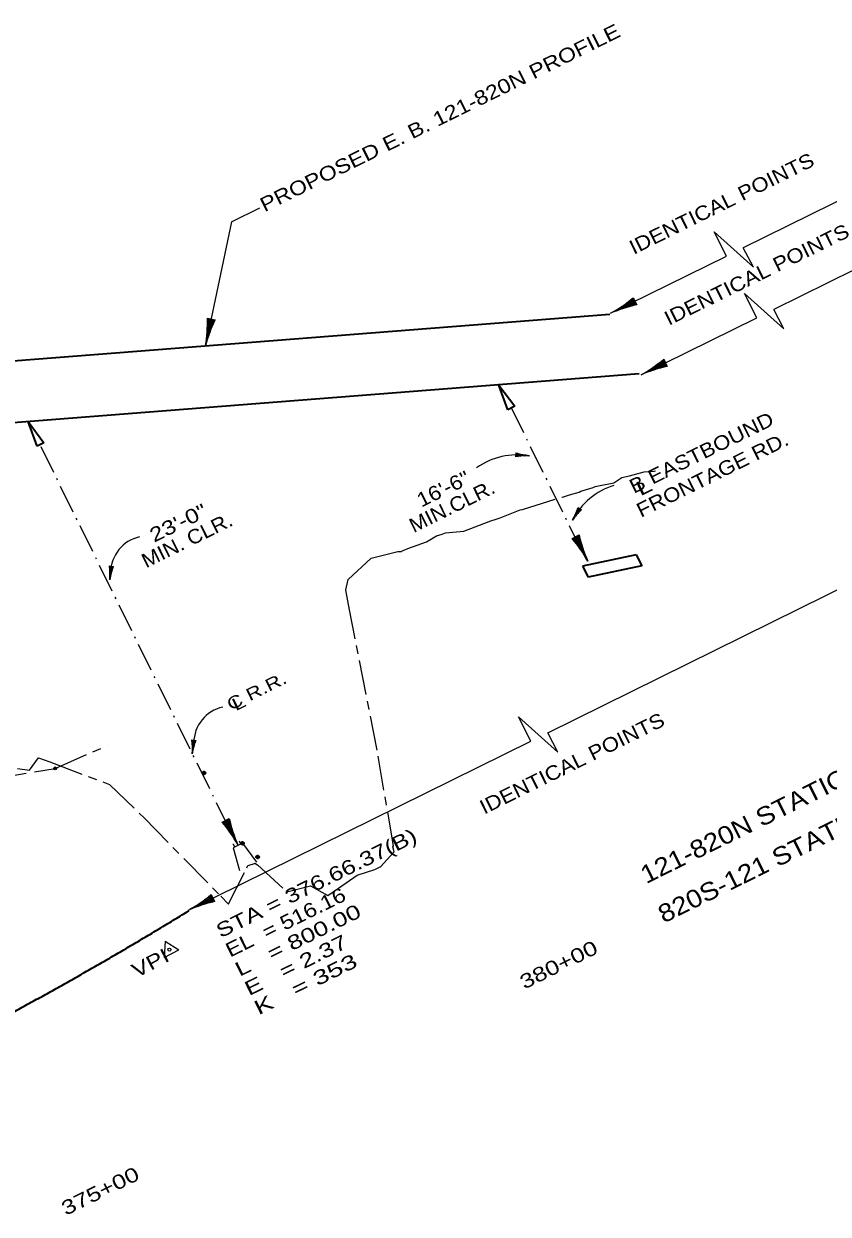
# Model space of a CAD drawing. Extents: x 2356431 to 2371438, y 6972864 to 6982525.
# Drawn here: x 2365783 to 2366570, y 6976942 to 6978106 of the extents above; entities that cross this region are included whole.
import ezdxf
from ezdxf.enums import TextEntityAlignment as Align

# ---------------------------------------------------------------- set-up
doc = ezdxf.new("R2010")
doc.units = 0
doc.header["$LTSCALE"] = 5.6
doc.header["$PDMODE"] = 32
doc.header["$PDSIZE"] = 2.8
for name, pattern in [('DASH_DOUBLE_DOT', [9.2, 5, -1.2, 0.3, -1.2, 0.3, -1.2]), ('DOT_DASHED', [7.7, 5, -1.2, 0.3, -1.2]), ('LONG_DASH_SHORT_DASH', [9.9, 6, -1.2, 1.5, -1.2]), ('LONG_DASHED', [7.5, 6, -1.5])]:
    doc.linetypes.add(name, pattern=pattern)
for name, color, linetype, lineweight in [('1', 7, 'Continuous', 25), ('2', 7, 'Continuous', 35), ('4', 7, 'LONG_DASHED', 35), ('44', 7, 'Continuous', 13), ('52', 7, 'Continuous', 25), ('53', 7, 'Continuous', 13), ('55', 7, 'Continuous', 13), ('61', 7, 'Continuous', 13)]:
    doc.layers.add(name, color=color, linetype=linetype, lineweight=lineweight)

msp = doc.modelspace()

# ---------------------------------------------------------------- linework, layer by layer
at = {"layer": '1'}
for p, q in [((2366380.572, 6977835.032), (2366358.046, 6977823.896)), ((2366381.015, 6977834.137), (2366365.579, 6977826.505)), ((2366380.129, 6977835.929), (2366366.95, 6977829.413)), ((2366379.687, 6977836.825), (2366372.019, 6977833.034)), ((2366381.459, 6977833.24), (2366372.741, 6977828.929)), ((2366379.243, 6977837.721), (2366376.4, 6977836.317)), ((2366381.902, 6977832.342), (2366377.632, 6977830.232)), ((2366378.933, 6977838.35), (2366382.327, 6977831.483)), ((2366410.296, 6977774.805), (2366387.77, 6977763.669)), ((2366410.739, 6977773.91), (2366395.303, 6977766.278)), ((2366409.853, 6977775.702), (2366396.674, 6977769.186)), ((2366409.411, 6977776.598), (2366401.743, 6977772.807)), ((2366411.183, 6977773.013), (2366402.465, 6977768.702)), ((2366408.967, 6977777.494), (2366406.124, 6977776.09)), ((2366411.626, 6977772.115), (2366407.356, 6977770.005)), ((2366408.657, 6977778.123), (2366412.051, 6977771.256)), ((2366319.08, 6977602.965), (2366325.95, 6977606.356)), ((2366319.708, 6977603.274), (2366321.11, 6977600.432)), ((2366320.604, 6977603.717), (2366324.39, 6977596.047)), ((2366321.501, 6977604.16), (2366328.006, 6977590.978)), ((2366322.399, 6977604.603), (2366333.52, 6977582.069)), ((2366323.296, 6977605.046), (2366330.916, 6977589.604)), ((2366324.191, 6977605.488), (2366328.495, 6977596.768)), ((2366325.088, 6977605.93), (2366327.196, 6977601.66)), ((2365967.732, 6977251.48), (2365945.206, 6977240.344)), ((2365968.175, 6977250.585), (2365952.739, 6977242.953)), ((2365967.289, 6977252.377), (2365954.11, 6977245.861)), ((2365966.847, 6977253.273), (2365959.179, 6977249.482)), ((2365968.619, 6977249.688), (2365959.901, 6977245.377)), ((2365966.403, 6977254.169), (2365963.56, 6977252.765)), ((2365969.062, 6977248.79), (2365964.792, 6977246.68)), ((2365966.094, 6977254.799), (2365969.488, 6977247.932))]:
    msp.add_line(p, q, dxfattribs=at)
at = {"layer": '1', "linetype": 'DOT_DASHED', "lineweight": 13}
msp.add_line((2365983.806, 6977319.446), (2365798.207, 6977695.508), dxfattribs=at)
at = {"layer": '1', "lineweight": 35}
for p, q in [((2366381.786, 6977587.003), (2366329.311, 6977575.832)), ((2366381.786, 6977587.003), (2366387.11, 6977576.215)), ((2366329.311, 6977575.832), (2366334.635, 6977565.044)), ((2366387.11, 6977576.215), (2366334.635, 6977565.044))]:
    msp.add_line(p, q, dxfattribs=at)
at = {"layer": '1', "linetype": 'LONG_DASH_SHORT_DASH'}
msp.add_line((2365813.438, 6977378.181), (2365864.499, 6977400.494), dxfattribs=at)
at = {"layer": '1', "linetype": 'LONG_DASHED'}
msp.add_line((2365710.484, 6977360.825), (2365813.438, 6977378.181), dxfattribs=at)
at = {"layer": '1', "lineweight": 13}
for p, q in [((2365976.874, 6977325.669), (2365983.744, 6977329.06)), ((2365977.501, 6977325.979), (2365978.904, 6977323.136)), ((2365978.398, 6977326.421), (2365982.183, 6977318.751)), ((2365979.296, 6977326.864), (2365985.801, 6977313.682)), ((2365980.193, 6977327.307), (2365991.313, 6977304.773)), ((2365981.089, 6977327.75), (2365988.71, 6977312.308)), ((2365981.985, 6977328.191), (2365986.289, 6977319.472)), ((2365982.882, 6977328.634), (2365984.99, 6977324.363)), ((2365993.659, 6977306.712), (2365992.964, 6977306.369)), ((2365993.659, 6977306.712), (2365994.156, 6977306.958)), ((2365994.942, 6977304.113), (2365993.724, 6977306.581)), ((2365987.919, 6977303.88), (2365987.271, 6977303.56)), ((2365987.587, 6977300.483), (2365993.832, 6977278.257)), ((2365989.202, 6977301.28), (2365987.917, 6977303.883)), ((2365987.919, 6977303.88), (2365988.329, 6977304.082)), ((2365996.668, 6977304.965), (2366010.512, 6977286.489))]:
    msp.add_line(p, q, dxfattribs=at)
at = {"layer": '1', "linetype": 'LONG_DASH_SHORT_DASH'}
msp.add_lwpolyline([(2365776.602, 6977378.009), (2365788.527, 6977376.384), (2365797.098, 6977388.517), (2365797.262, 6977388.568), (2365808.166, 6977384.427), (2365866.729, 6977362.512), (2365900.468, 6977329.749), (2365975.432, 6977253.209), (2365982.865, 6977245.28), (2365982.974, 6977245.284), (2365983.329, 6977246.258), (2366000.892, 6977280.846), (2366001.988, 6977283.075), (2366002.119, 6977283.126), (2366003.234, 6977283.51), (2366008.318, 6977285.254), (2366008.72, 6977285.478), (2366011.481, 6977283.796), (2366040.032, 6977257.402), (2366063.277, 6977263.159), (2366080.054, 6977253.838), (2366090.534, 6977261.093), (2366108.85, 6977273.754), (2366126.118, 6977279.373), (2366131.309, 6977281.735), (2366131.533, 6977281.892), (2366144.75, 6977296.338), (2366145.157, 6977296.574), (2366143.591, 6977301.548), (2366144.328, 6977302.314), (2366128.386, 6977396.093), (2366101.51, 6977533.231), (2366098.726, 6977547.148), (2366097.801, 6977552.856), (2366100.109, 6977562.969), (2366122.635, 6977583.654), (2366127.922, 6977585.01), (2366148.734, 6977590.07), (2366151.866, 6977590.166), (2366152.085, 6977590.286), (2366152.493, 6977590.5), (2366152.935, 6977590.711), (2366155.594, 6977591.787), (2366158.36, 6977593.095), (2366176.56, 6977599.786), (2366186.396, 6977605.545), (2366191.97, 6977607.314), (2366195.282, 6977608.512), (2366213.202, 6977610.011), (2366239.638, 6977620.057), (2366244.672, 6977621.945), (2366248.72, 6977623.235), (2366268.169, 6977630.874), (2366270.468, 6977631.435), (2366309.663, 6977643.381), (2366316.578, 6977645.503), (2366325.961, 6977648.365), (2366327.702, 6977649.289), (2366339.831, 6977652.825), (2366341.723, 6977653.668), (2366359.811, 6977657.449), (2366367.679, 6977662.608), (2366375.096, 6977664.326), (2366389.651, 6977668.144), (2366399.335, 6977668.772), (2366400.712, 6977669.122)], dxfattribs=at)
at = {"layer": '1'}
for centre, start, end in [((2366286.411, 6977949.256), 299.14996, 309.83601), ((2366414.27, 6977690.628), 102.77679, 113.46284), ((2366316.135, 6977889.03), 299.14996, 309.83601), ((2366443.993, 6977630.401), 102.77679, 113.46284), ((2366208.112, 6977510.518), 29.11143, 39.79748), ((2366466.826, 6977638.202), 192.73827, 203.42432), ((2365873.572, 6977365.705), 299.14996, 309.83601), ((2366001.43, 6977107.076), 102.77679, 113.46284)]:
    msp.add_arc(centre, 144.431, start, end, dxfattribs=at)
at = {"layer": '1', "lineweight": 13}
for centre, radius, start, end in [((2366265.859, 6977614.665), 70.06, 80.64351, 125.05271), ((2366381.09, 6977587.98), 70.06, 107.48304, 151.89224), ((2365903.913, 6977569.144), 36.259, 102.58429, 179.17976), ((2365985.245, 6977402.662), 36.259, 102.58429, 179.17976), ((2365865.905, 6977233.222), 144.431, 29.11143, 39.79748), ((2366124.619, 6977360.906), 144.431, 192.73827, 203.42432)]:
    msp.add_arc(centre, radius, start, end, dxfattribs=at)
at = {"layer": '2', "lineweight": 13}
for p, q in [((2365986.056, 6977912.411), (2366013.825, 6977926.116)), ((2365986.056, 6977912.411), (2365960.543, 6977791.527)), ((2365962.341, 6977818.364), (2365969.834, 6977816.769))]:
    msp.add_line(p, q, dxfattribs=at)
at = {"layer": '2', "lineweight": 25}
for p, q in [((2366295.248, 6977412.955), (2366661.345, 6977593.635)), ((2365943.924, 6977239.565), (2366278.772, 6977404.824))]:
    msp.add_line(p, q, dxfattribs=at)
msp.add_lwpolyline([(2366278.772, 6977404.824), (2366266.67, 6977428.47), (2366305.113, 6977393.953)], dxfattribs=at)
at = {"layer": '2', "lineweight": 13}
for centre, start, end in [((2365817.959, 6977814.557), 350.82423, 1.51028), ((2366100.141, 6977754.478), 154.45106, 165.13711)]:
    msp.add_arc(centre, 144.431, start, end, dxfattribs=at)
at = {"layer": '2'}
msp.add_spline([(2365561.252, 6977034.695), (2365575.796, 6977041.379), (2365590.308, 6977048.127), (2365604.788, 6977054.941), (2365619.235, 6977061.819), (2365633.651, 6977068.763), (2365648.034, 6977075.771), (2365662.386, 6977082.845), (2365676.705, 6977089.985), (2365690.992, 6977097.189), (2365705.247, 6977104.458), (2365719.47, 6977111.792), (2365733.66, 6977119.192), (2365747.819, 6977126.656), (2365761.945, 6977134.186), (2365776.039, 6977141.781), (2365790.101, 6977149.44), (2365804.131, 6977157.166), (2365818.129, 6977164.956), (2365832.095, 6977172.812), (2365846.028, 6977180.732), (2365859.93, 6977188.717), (2365873.799, 6977196.768), (2365887.636, 6977204.883), (2365901.441, 6977213.065), (2365915.214, 6977221.311), (2365928.954, 6977229.622), (2365942.663, 6977237.998), (2365944.224, 6977238.957)], degree=3, dxfattribs=at)
at = {"layer": '4'}
for p in [(2365959.001, 6977373.629), (2365996.556, 6977304.91), (2366011.471, 6977291.521)]:
    msp.add_point(p, dxfattribs=at)
at = {"layer": '44'}
for p, q in [((2365965.96, 6977817.594), (2365960.727, 6977793.015)), ((2365964.982, 6977817.804), (2365961.921, 6977803.423)), ((2365964.004, 6977818.012), (2365962.222, 6977809.643)), ((2365963.026, 6977818.219), (2365962.366, 6977815.117)), ((2365966.94, 6977817.384), (2365963.351, 6977800.542)), ((2365967.917, 6977817.177), (2365965.892, 6977807.666)), ((2365968.896, 6977816.969), (2365967.903, 6977812.31)), ((2365996.556, 6977304.91), (2365987.587, 6977300.483))]:
    msp.add_line(p, q, dxfattribs=at)
at = {"layer": '44', "linetype": 'DOT_DASHED'}
msp.add_line((2366259.072, 6977731.567), (2366334.052, 6977579.64), dxfattribs=at)
at = {"layer": '52'}
msp.add_point((2365813.438, 6977378.181), dxfattribs=at)
at = {"layer": '53', "lineweight": 25}
for p, q in [((2366625.795, 6977955.893), (2366486.492, 6977887.142)), ((2366655.519, 6977895.666), (2366516.216, 6977826.915)), ((2366305.113, 6977393.953), (2366295.248, 6977412.956))]:
    msp.add_line(p, q, dxfattribs=at)
at = {"layer": '53', "lineweight": 35}
for p, q in [((2365514.614, 6977756.311), (2366355.88, 6977822.203)), ((2365519.299, 6977696.494), (2366384.586, 6977764.268))]:
    msp.add_line(p, q, dxfattribs=at)
at = {"layer": '53', "lineweight": 25}
for points in [[(2366356.763, 6977823.116), (2366470.016, 6977879.011), (2366457.912, 6977902.657), (2366496.356, 6977868.139), (2366486.492, 6977887.142)], [(2366386.487, 6977762.889), (2366499.74, 6977818.784), (2366487.636, 6977842.43), (2366526.08, 6977807.912), (2366516.216, 6977826.915)]]:
    msp.add_lwpolyline(points, dxfattribs=at)
at = {"layer": '53', "linetype": 'DASH_DOUBLE_DOT', "lineweight": 35}
for points in [[(2366256.214, 6977728.815), (2366247.493, 6977752.876), (2366262.897, 6977732.174)], [(2365795.804, 6977693.146), (2365787.083, 6977717.207), (2365802.487, 6977696.505)]]:
    msp.add_lwpolyline(points, close=True, dxfattribs=at)
at = {"layer": '55'}
for p, q in [((2366264.15, 6977686.736), (2366263.832, 6977682.919)), ((2366263.871, 6977683.398), (2366266.245, 6977683.199)), ((2366263.914, 6977683.897), (2366268.759, 6977683.492)), ((2366263.955, 6977684.396), (2366272.535, 6977683.678)), ((2366263.997, 6977684.894), (2366276.517, 6977683.846)), ((2366264.041, 6977685.392), (2366271.363, 6977684.779)), ((2366264.083, 6977685.889), (2366268.342, 6977685.533)), ((2366264.122, 6977686.389), (2366265.703, 6977686.255)), ((2366326.057, 6977632.444), (2366322.089, 6977626.259)), ((2366325.637, 6977632.713), (2366323.328, 6977629.115)), ((2366325.216, 6977632.986), (2366324.361, 6977631.65)), ((2366324.923, 6977633.175), (2366328.146, 6977631.105)), ((2366326.478, 6977632.176), (2366319.695, 6977621.601)), ((2366326.899, 6977631.906), (2366322.251, 6977624.658)), ((2366327.321, 6977631.634), (2366324.695, 6977627.543)), ((2366327.742, 6977631.366), (2366326.456, 6977629.36)), ((2365866.551, 6977576.095), (2365870.357, 6977575.664)), ((2365866.899, 6977576.055), (2365866.72, 6977574.481)), ((2365867.395, 6977575.999), (2365866.914, 6977571.749)), ((2365868.39, 6977575.886), (2365866.976, 6977563.401)), ((2365867.893, 6977575.943), (2365867.066, 6977568.64)), ((2365868.886, 6977575.83), (2365867.918, 6977567.275)), ((2365869.383, 6977575.775), (2365868.836, 6977570.943)), ((2365869.88, 6977575.718), (2365869.612, 6977573.35)), ((2365947.197, 6977405.941), (2365951.003, 6977405.51)), ((2365947.545, 6977405.901), (2365947.366, 6977404.327)), ((2365948.041, 6977405.845), (2365947.56, 6977401.595)), ((2365949.036, 6977405.732), (2365947.622, 6977393.247)), ((2365948.539, 6977405.789), (2365947.712, 6977398.486)), ((2365949.532, 6977405.676), (2365948.564, 6977397.121)), ((2365950.029, 6977405.621), (2365949.482, 6977400.789)), ((2365950.526, 6977405.564), (2365950.258, 6977403.196))]:
    msp.add_line(p, q, dxfattribs=at)
for centre, start, end in [((2366274.818, 6977611.545), 88.06363, 98.74968), ((2366286.838, 6977755.296), 251.69047, 262.37652), ((2366256.706, 6977656.869), 330.15924, 340.84529), ((2366378.118, 6977578.971), 133.78607, 144.47212), ((2365794.884, 6977567.207), 356.383, 7.06905), ((2365938.221, 6977550.976), 160.00983, 170.69588), ((2365875.53, 6977397.053), 356.383, 7.06905), ((2366018.867, 6977380.822), 160.00983, 170.69588)]:
    msp.add_arc(centre, 72.216, start, end, dxfattribs=at)
at = {"layer": '61'}
for p, q in [((2365920.953, 6977209.239), (2365920.253, 6977193.097)), ((2365920.953, 6977209.239), (2365934.585, 6977200.566)), ((2365920.253, 6977193.097), (2365934.585, 6977200.566))]:
    msp.add_line(p, q, dxfattribs=at)
msp.add_circle((2365925.257, 6977200.96), 1.5, dxfattribs=at)

# ---------------------------------------------------------------- texts
at = {"layer": '1'}
for s, height, width, p in [('B EASTBOUND', 14, 1.15, (2366448.669, 6977680.632)), ('FRONTAGE RD.', 14, 1.15, (2366459.339, 6977659.133)), ('16\'-6"', 14, 1.15, (2366196.101, 6977645.175)), ('MIN.CLR.', 14, 1.1, (2366204.659, 6977628.21)), ('L', 14, 1.4, (2366392.428, 6977647.312)), ('23\'-0"', 14, 1.25, (2365936.933, 6977611.951)), ('MIN. CLR.', 14, 1.1, (2365945.49, 6977594.984)), ('C R.R.', 12, 1.3, (2366013.184, 6977448.309)), ('L', 12, 1.4, (2365995.683, 6977436.768))]:
    msp.add_text(s, height=height, rotation=26.268, dxfattribs=dict(at, width=width)).set_placement(p, align=Align.CENTER)
at = {"layer": '2'}
for s, height, width, p in [('PROPOSED E. B. 121-820N PROFILE', 14, 1.2, (2366192.925, 6978008.046)), ('IDENTICAL POINTS', 14, 1.15, (2366468.375, 6977924.182)), ('IDENTICAL POINTS', 14, 1.15, (2366502.669, 6977854.695)), ('IDENTICAL POINTS', 14, 1.15, (2366322.095, 6977376.801)), ('121-820N STATIONING', 17.5, 1.15, (2366521.521, 6977329.097)), ('820S-121 STATIONING', 17.5, 1.15, (2366538.107, 6977290.312))]:
    msp.add_text(s, height=height, rotation=26.268, dxfattribs=dict(at, width=width)).set_placement(p, align=Align.CENTER)
at = {"layer": '52'}
for s, width, p in [('STA = 376.66.37(B)', 1.3, (2365975.256, 6977211.91)), ('EL  = 516.16', 1.2, (2365984.549, 6977193.079)), ('L   = 800.00', 1.35, (2365993.843, 6977174.248)), ('E   = 2.37', 1.35, (2366003.137, 6977155.417)), ('K   = 353', 1.45, (2366012.431, 6977136.586))]:
    msp.add_text(s, height=14, rotation=26.268, dxfattribs=dict(at, width=width)).set_placement(p)
at = {"layer": '53', "width": 1.3}
for s, p in [('380+00', (2366309.037, 6977179.959)), ('375+00', (2365860.649, 6976958.665))]:
    msp.add_text(s, height=14, rotation=26.268, dxfattribs=at).set_placement(p, align=Align.CENTER)
at = {"layer": '61', "width": 1.25}
msp.add_text('VPI', height=14, rotation=27.529, dxfattribs=at).set_placement((2365909.843, 6977181.629), align=Align.CENTER)

doc.saveas('drawing.dxf')
